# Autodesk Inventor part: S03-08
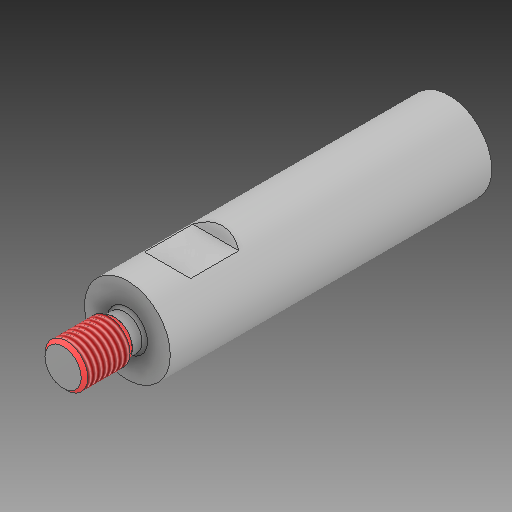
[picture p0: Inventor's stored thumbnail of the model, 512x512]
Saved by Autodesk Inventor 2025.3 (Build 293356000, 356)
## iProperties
Created: 2025-05
Part Number: S03-08
Material: Všeobecné
Document SubType Name: Modeling
Designer: Patrik
Density: 1 g/cm^3
Appearance: Výchozí
Mass: 99.7481 g
Surface Area: 148.744 cm^2
Volume: 99.7481 cm^3
Description: Táhlo vyhazovacího paketu
Stock Number: E 1928/32x120
User Status: 1.7131
Sending System: KiM GmbH
Major Version: 4.0
Minor Version: 0.0
Format Version: 0.0
Product Id: KiM GmbH
cc_prop_force_one_body: 1
Hersteller: Meusburger
Material: 1.7131
Bestellnummer: E 1928/32/120
Teilenummer: E 1928/32/120
Beschreibung: Auflagebolzen _ Support bolt
Author: Patrik
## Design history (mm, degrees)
feature "E 1928_32_120_1_1:1"
feature "Závit1" dims "d0" = 15.775, "d1" = 0
node "Těleso1"
